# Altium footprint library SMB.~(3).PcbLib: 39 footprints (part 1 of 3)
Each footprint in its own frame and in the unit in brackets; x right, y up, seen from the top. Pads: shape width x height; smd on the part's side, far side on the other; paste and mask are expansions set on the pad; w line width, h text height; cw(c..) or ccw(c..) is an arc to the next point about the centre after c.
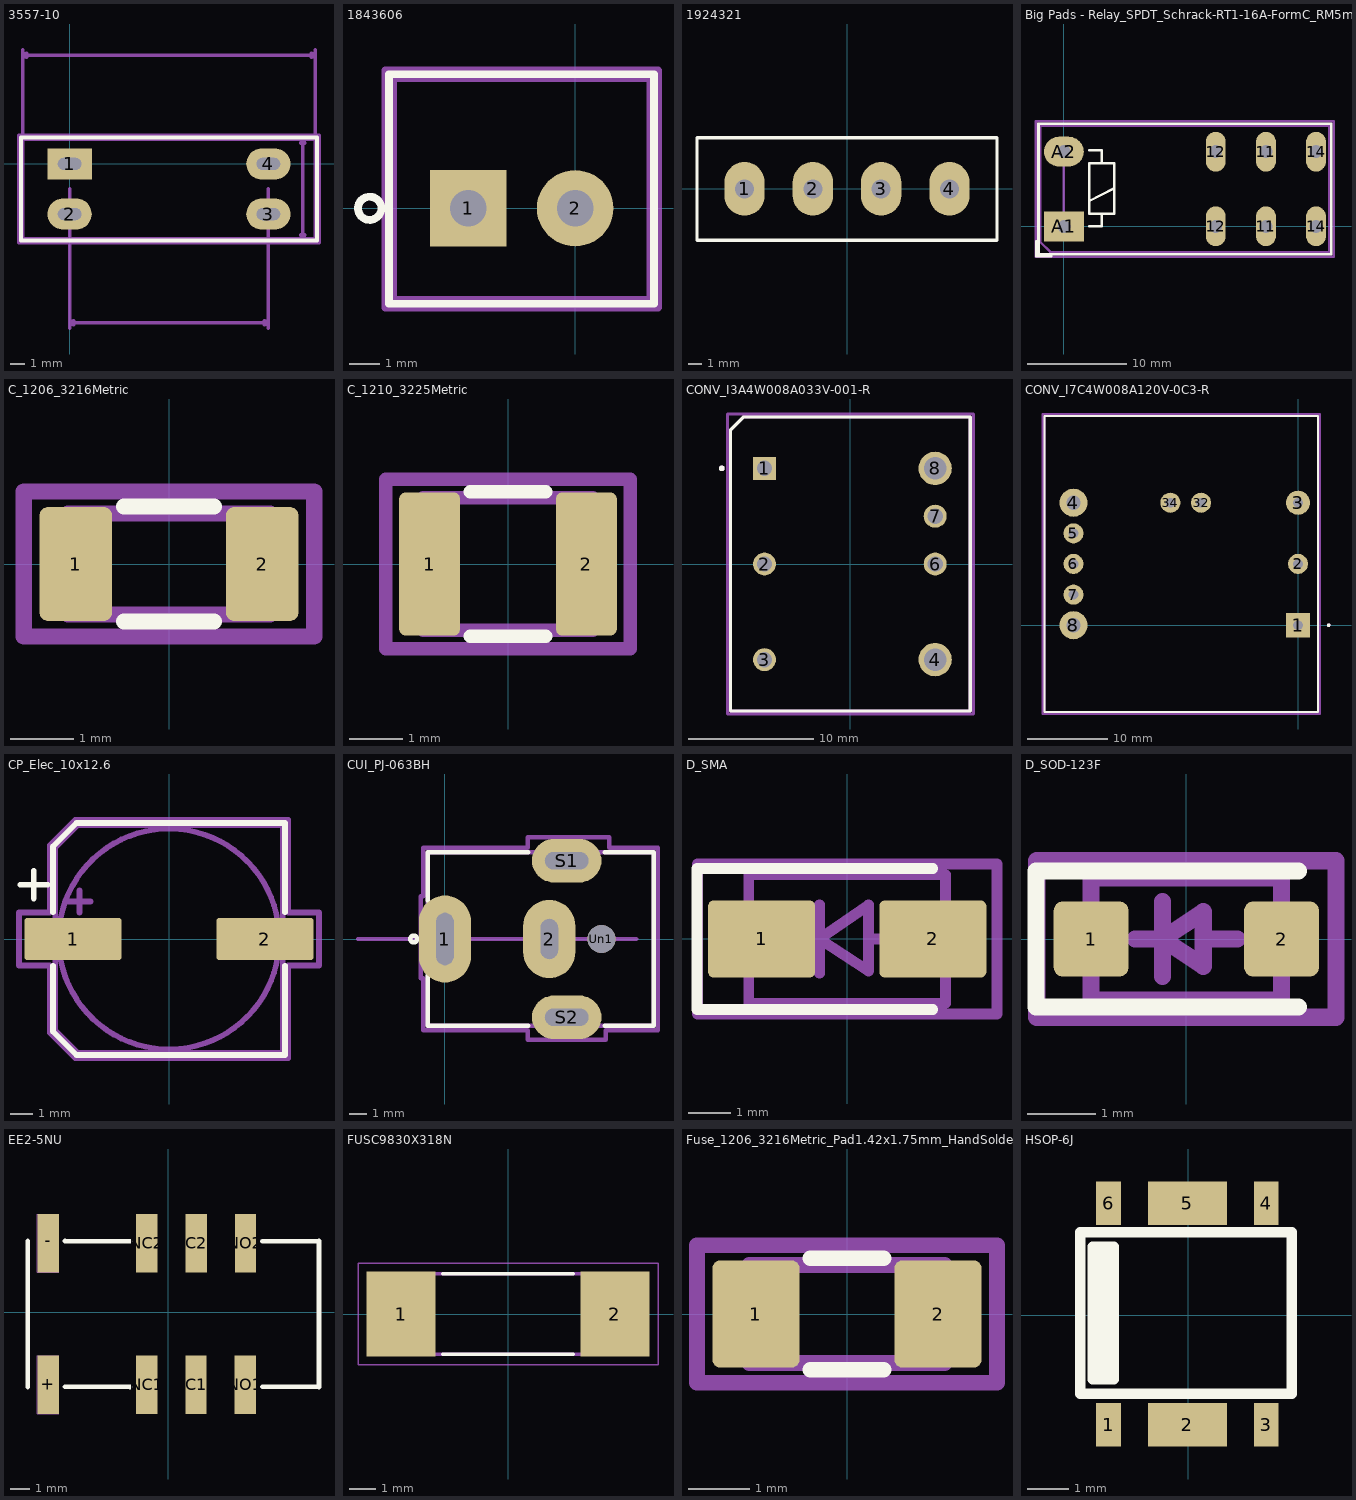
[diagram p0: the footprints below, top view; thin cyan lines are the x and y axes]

## 3557-10 [mm]
pads (4):
  rect 3x2.108 hole 0.8 slot 1.6 at 0 deg: 1(0,0)
  rrect100% 3x2.108 hole 0.8 slot 1.6 at 0 deg: 2(0,-3.404) 3(13.462,-3.404) 4(13.462,0)
F.SilkS:
  lines w0.254: -3.302,-5.194 16.764,-5.194 16.764,1.791 -3.302,1.791 -3.302,-5.194
  text "*" at -0.122,-0.117 h1
F.Fab:
  lines w0.254: -3.175,-5.067 16.637,-5.067 16.637,1.664 -3.175,1.664 -3.175,-5.067
  text "*" at -0.122,-0.117 h1
F.CrtYd:
  lines w0.254: -3.429,-5.321 16.891,-5.321 ; -3.429,-5.321 16.891,-5.321 ; -3.429,-5.321 -3.429,1.918 ; -3.429,-5.321 -3.429,1.918 ; -3.429,1.918 16.891,1.918 ; -3.429,1.918 16.891,1.918 ; 16.891,-5.321 16.891,1.918 ; 16.891,-5.321 16.891,1.918
Cmts.User:
  lines w0.254: -3.175,-1.702 -3.175,7.734 ; 0,-11.138 0,-1.702 ; 6.731,-5.067 16.167,-5.067 ; 6.731,1.664 16.167,1.664 ; 13.462,-11.138 13.462,-1.702 ; 16.637,-1.702 16.637,7.734 ; -3.175,7.353 16.637,7.353 ; -3.175,7.353 -2.921,7.226 -2.921,7.48 -3.175,7.353 ; 0,-10.757 13.462,-10.757 ; 0,-10.757 0.254,-10.884 0.254,-10.63 0,-10.757 ; 13.462,-10.757 13.208,-10.884 13.208,-10.63 13.462,-10.757 ; 15.786,-5.067 15.913,-4.813 15.659,-4.813 15.786,-5.067 ; 15.786,-5.067 15.786,1.664 ; 15.786,1.664 15.913,1.41 15.659,1.41 15.786,1.664 ; 16.637,7.353 16.383,7.226 16.383,7.48 16.637,7.353
  text "Copyright 2021 Accelerated Designs. All rights reserved." at -0.861,-0.049 h0.13
3D body "Universal Car Fuse Holder PCB v1.step": height 2.45, standoff -7.8, extent -3.371,-5.182 16.629,1.818
3D body "User Library-ATO-ATC STANDARD BLADE FUSE.step": height -0.49, standoff -19.29, extent -2.743,-4.343 16.307,0.737

## 1843606 [mm]
pads (2):
  rect 2.5x2.5 hole 1.194: 1(-3.5,0)
  round 2.5 hole 1.194: 2(0,0)
F.SilkS:
  circle w0.254: c-6.716,0 r0.381
  lines w0.254: -6.081,-3.116 2.581,-3.116 2.581,4.377 -6.081,4.377 -6.081,-3.116
B.SilkS:
  circle w0.254: c-6.716,0 r0.381
F.Fab:
  lines w0.254: -5.954,-2.989 2.454,-2.989 2.454,4.25 -5.954,4.25 -5.954,-2.989
  text "*" at -0.122,-0.117 h1
F.CrtYd:
  lines w0.254: -6.208,-3.243 2.708,-3.243 ; -6.208,-3.243 2.708,-3.243 ; -6.208,-3.243 -6.208,4.504 ; -6.208,-3.243 -6.208,4.504 ; -6.208,4.504 2.708,4.504 ; -6.208,4.504 2.708,4.504 ; 2.708,-3.243 2.708,4.504 ; 2.708,-3.243 2.708,4.504
3D body "1843606.stp": height 9.2, standoff -3.4, extent -5.927,-3.034 2.473,4.216

## 1924321 [mm]
pads (4):
  rrect100% 3x4 hole 1.4: 1(-7.62,0) 2(-2.54,0) 3(2.54,0) 4(7.62,0)
F.SilkS:
  lines w0.254: -11.16,-3.82 11.16,-3.82 ; -11.16,-3.8 -11.16,3.8 11.16,3.8 11.16,-3.8
3D body "1924321.stp": height 12, standoff -3.9, extent -11.135,-4.775 11.185,3.825

## Big Pads - Relay_SPDT_Schrack-RT1-16A-FormC_RM5mm [mm]
pads (8):
  rrect100% 2x4 hole 1.3: 11(20.3,0) 11(20.3,7.5) 12(15.26,0) 12(15.26,7.5) 14(25.34,0) 14(25.34,7.5)
  rect 4x3 hole 1.3: A1(0,0)
  rrect100% 4x3 hole 1.3: A2(0,7.5)
F.SilkS:
  lines w0.254: -2.75,-1.5 -2.75,-3 -1.25,-3 ; 2.54,0 3.81,0 3.81,1.27 ; 2.54,2.54 5.08,3.81 ; 2.54,7.62 3.81,7.62 3.81,6.35 ; 3.81,1.27 2.54,1.27 2.54,6.35 5.08,6.35 5.08,1.27 3.81,1.27 ; -2.55,-2.8 -2.55,10.3 26.85,10.3 26.85,-2.8 -2.55,-2.8
F.Fab:
  lines w0.254: 0,1.27 0,6.35 ; -2.35,-1.6 -2.35,10.1 26.65,10.1 26.65,-2.6 -1.35,-2.6 -2.35,-1.6
  text "'.Designator'" at 10.626,3.412 h1
F.CrtYd:
  lines w0.254: -2.8,-3.05 -2.8,10.55 27.1,10.55 27.1,-3.05 -2.8,-3.05
3D body: height 12, standoff 0.1, extent -2.337,-2.769 26.848,10.185

## C_1206_3216Metric [mm]
pads (2):
  rrect22% 1.15x1.8 smd mask+0: 1(-1.475,0) 2(1.475,0)
F.SilkS:
  lines w0.254: -0.711,-0.91 0.711,-0.91 ; -0.711,0.91 0.711,0.91
F.Fab:
  lines w0.254: -1.6,-0.8 1.6,-0.8 1.6,0.8 -1.6,0.8 -1.6,-0.8
  text "'.Designator'" at -0.33,-0.227 h0.8
F.CrtYd:
  lines w0.254: -2.3,-1.15 2.3,-1.15 2.3,1.15 -2.3,1.15 -2.3,-1.15
3D body "C_1206_3216Metric.step": height 1.6, standoff 0, extent -1.602,-0.811 1.598,0.789

## C_1210_3225Metric [mm]
pads (2):
  rrect22% 1.15x2.7 smd mask+0: 1(-1.475,0) 2(1.475,0)
F.SilkS:
  lines w0.254: -0.711,-1.36 0.711,-1.36 ; -0.711,1.36 0.711,1.36
F.Fab:
  lines w0.254: -1.6,-1.25 -1.6,1.25 1.6,1.25 1.6,-1.25 -1.6,-1.25
  text "'.Designator'" at -0.205,-0.228 h0.8
F.CrtYd:
  lines w0.254: -2.3,-1.6 -2.3,1.6 2.3,1.6 2.3,-1.6 -2.3,-1.6

## CONV_I3A4W008A033V-001-R [mm]
pads (7):
  rect 1.83x1.83 hole 1.22: 1(-6.85,7.62)
  round 1.83 hole 1.22: 2(-6.85,0) 3(-6.85,-7.62) 6(6.75,0) 7(6.75,3.81)
  round 2.655 hole 1.77: 4(6.75,-7.62) 8(6.75,7.62)
F.SilkS:
  circle w0.254: c-10.25,7.62 r0.1
  lines w0.254: -9.55,-11.7 9.55,-11.7 9.55,11.7 -8.55,11.7 -9.55,10.7 -9.55,-11.7
F.Fab:
  circle w0.254: c-10.25,7.62 r0.1
  lines w0.254: -9.55,-11.7 9.55,-11.7 9.55,11.7 -8.55,11.7 -9.55,10.7 -9.55,-11.7
F.CrtYd:
  lines w0.254: -9.8,-11.95 9.8,-11.95 9.8,11.95 -9.8,11.95 -9.8,-11.95
3D body "I3A4W008A033V-001-R.step": height 9.76, standoff -3.47, extent -9.511,-11.724 9.539,11.645

## CONV_I7C4W008A120V-0C3-R [mm]
pads (10):
  rect 3x3 hole 1.22 paste-2539.97 mask+0: 1(0,0)
  round 2.5 hole 1.22 paste-2539.97 mask+0: 2(0,7.62) 5(-27.94,11.43) 6(-27.94,7.62) 7(-27.94,3.81) 32(-12.07,15.24) 34(-15.88,15.24)
  round 3 hole 1.22 paste-2539.97 mask+0: 3(0,15.24)
  round 3.5 hole 1.77 paste-2539.97 mask+0: 4(-27.94,15.24) 8(-27.94,0)
F.SilkS:
  circle w0.254: c3.81,0 r0.1
  lines w0.254: -31.54,-10.8 2.5,-10.8 2.5,26.03 -31.54,26.03 -31.54,-10.8
B.Fab:
  circle w0.254: c3.81,0 r0.1
  lines w0.254: -31.54,-10.8 2.5,-10.8 2.5,26.03 -31.54,26.03 -31.54,-10.8
B.CrtYd:
  lines w0.254: -31.79,-11.05 2.75,-11.05 2.75,26.28 -31.79,26.28 -31.79,-11.05
3D body "I7C4W008A120V-0C3-R.step": height 13.46, standoff -4.57, extent -31.496,-10.795 2.54,26.035

## CP_Elec_10x12.6 [mm]
pads (2):
  rrect13% 4.4x1.9 smd mask+0: 1(-4.35,0) 2(4.35,0)
F.SilkS:
  lines w0.254: -6.75,2.46 -5.5,2.46 ; -6.125,1.835 -6.125,3.085 ; -5.26,-1.21 -5.26,-4.196 -4.196,-5.26 5.26,-5.26 5.26,-1.21 ; -5.26,1.21 -5.26,4.196 -4.196,5.26 5.26,5.26 5.26,1.21
F.Fab:
  circle w0.254: c0,0 r5
  lines w0.254: -4.558,1.7 -3.558,1.7 ; -4.058,1.2 -4.058,2.2 ; -5.15,-4.15 -4.15,-5.15 5.15,-5.15 5.15,5.15 -4.15,5.15 -5.15,4.15 -5.15,-4.15
  text "'.Designator'" at -0.404,-0.286 h1
F.CrtYd:
  lines w0.254: -6.8,-1.2 -5.4,-1.2 -5.4,-4.25 -4.25,-5.4 5.4,-5.4 5.4,-1.2 6.8,-1.2 6.8,1.2 5.4,1.2 5.4,5.4 -4.25,5.4 -5.4,4.25 -5.4,1.2 -6.8,1.2 -6.8,-1.2

## CUI_PJ-063BH [mm]
pads (5):
  rrect100% 3x5 hole 3 slot 1 at 0 deg: 1(0,0)
  rrect100% 3x4.5 hole 2.3 slot 1 at 0 deg: 2(6,0)
  rrect100% 4x2.5 hole 1 slot 2.5 at 0 deg: S1(7,4.5) S2(7,-4.5)
  round 1.6 hole 1.6: Un1(9,0)
F.SilkS:
  circle w0.254: c-1.8,0 r0.2
  lines w0.254: -1,-2.1 -1,-5 4.8,-5 ; -1,2.2 -1,5 4.8,5 ; 9.2,-5 12,-5 12,5 9.2,5
F.Fab:
  lines w0.254: -1,-5 12,-5 12,5 -1,5 -1,-5
F.CrtYd:
  lines w0.254: -1.4,-2.25 -1.25,-2.25 -1.25,-5.25 4.75,-5.25 4.75,-5.8 9.25,-5.8 9.25,-5.25 12.25,-5.25 12.25,5.25 9.45,5.25 9.45,5.85 4.75,5.85 4.75,5.25 -1.25,5.25 -1.25,2.45 -1.4,2.45 -1.4,-2.25
Dwgs.User:
  lines w0.254: -5,0 11,0
3D body "CUI_DEVICES_PJ-063BH.step": height 9, standoff -3, extent -0.963,-5.525 12.037,4.775

## D_SMA [mm]
pads (2):
  rrect14% 2.5x1.8 smd mask+0: 1(-2,0) 2(2,0)
F.SilkS:
  lines w0.254: 2,-1.65 -3.51,-1.65 -3.51,1.65 2,1.65
F.Fab:
  lines w0.254: -1.551,-0.001 -0.649,-0.001 ; -0.649,-0.801 -0.649,0.799 ; 0.501,-0.001 1.499,-0.001 ; -0.649,-0.001 0.501,0.799 0.501,-0.75 -0.649,-0.001 ; -2.3,-1.5 2.3,-1.5 2.3,1.5 -2.3,1.5 -2.3,-1.5
  text "'.Designator'" at 0.279,2.78 h1
F.CrtYd:
  lines w0.254: -3.5,-1.75 3.5,-1.75 3.5,1.75 -3.5,1.75 -3.5,-1.75

## D_SOD-123F [mm]
pads (2):
  rrect23% 1.1x1.1 smd mask+0: 1(-1.4,0) 2(1.4,0)
F.SilkS:
  lines w0.254: 1.65,-1 -2.21,-1 -2.21,1 1.65,1
F.Fab:
  lines w0.254: -0.75,0 -0.35,0 ; -0.35,-0.55 -0.35,0 ; -0.35,0.55 -0.35,0 ; 0.25,0 0.75,0 ; -0.35,0 0.25,0.4 0.25,-0.4 -0.35,0 ; -1.4,-0.9 -1.4,0.9 1.4,0.9 1.4,-0.9 -1.4,-0.9
  text "'.Designator'" at -0.412,1.62 h1
F.CrtYd:
  lines w0.254: -2.2,-1.15 -2.2,1.15 2.2,1.15 2.2,-1.15 -2.2,-1.15

## EE2-5NU [mm]
pads (8):
  rect 1.1x3 smd: +(-6.198,-3.728) -(-6.193,3.55) C1(1.422,-3.728) C2(1.427,3.55) NC1(-1.118,-3.728) NC2(-1.113,3.55) NO1(3.962,-3.728) NO2(3.967,3.55)
F.SilkS:
  lines w0.254: -7.246,-3.839 -7.246,3.661 ; -5.333,-3.837 -1.981,-3.842 ; -5.32,3.664 -1.976,3.659 ; 4.833,3.659 7.749,3.659 ; 4.836,-3.837 7.756,-3.831 ; 7.754,-3.839 7.754,3.661
F.Fab:
  lines w0.001: -6.751,-5.234 -5.641,-5.234 -5.641,-2.234 -6.751,-2.234 -6.751,-5.234 ; -6.751,2.056 -5.641,2.056 -5.641,5.056 -6.751,5.056 -6.751,2.056
3D body "User Library-EE2-5NU.step": height 10, standoff 0, extent -7.518,-4.852 7.482,4.648

## FUSC9830X318N [mm]
pads (2):
  rect 2.62x3.2 smd: 1(-4.047,0) 2(4.047,0)
F.SilkS:
  lines w0.127: -2.47,-1.52 2.47,-1.52 ; -2.47,1.52 2.47,1.52
F.Fab:
  lines w0.127: -4.9,-1.52 4.9,-1.52 4.9,1.52 -4.9,1.52 -4.9,-1.52
F.CrtYd:
  lines w0.05: -5.68,-1.92 5.68,-1.92 5.68,1.92 -5.68,1.92 -5.68,-1.92
3D body "0678L9250-02.step": height 2.83, standoff -0.23, extent -4.849,-1.626 4.951,1.554

## Fuse_1206_3216Metric_Pad1.42x1.75mm_HandSolder [mm]
pads (2):
  rrect18% 1.425x1.75 smd mask+0: 1(-1.488,0) 2(1.488,0)
F.SilkS:
  lines w0.254: -0.602,-0.91 0.602,-0.91 ; -0.602,0.91 0.602,0.91
F.Fab:
  lines w0.254: -1.6,-0.8 1.6,-0.8 1.6,0.8 -1.6,0.8 -1.6,-0.8
  text "'.Designator'" at 0.318,0.228 h0.8
F.CrtYd:
  lines w0.254: -2.45,-1.12 2.45,-1.12 2.45,1.12 -2.45,1.12 -2.45,-1.12

## HSOP-6J [mm]
pads (6):
  rect 0.6x1.05 smd: 1(-1.93,-2.65) 3(1.88,-2.65) 4(1.88,2.7) 6(-1.93,2.7)
  rect 1.9x1.05 smd: 2(-0.025,-2.65) 5(-0.025,2.7)
F.SilkS:
  region: -1.81,-1.55 -2.31,-1.55 -2.31,1.65 -1.81,1.65
  lines w0.254: -2.62,-1.9 2.5,-1.9 2.5,2 -2.62,2 -2.62,-1.9 ; -2.31,-1.55 -1.81,-1.55 -1.81,1.65 -2.31,1.65 -2.31,-1.55
F.Fab:
  text "'.Designator'" at -1.389,-7.578 h1
3D body "HSOP-6J.STEP": height 1.65, standoff 0, extent -2.485,-3.025 2.535,2.975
